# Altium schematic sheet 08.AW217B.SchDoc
size A4; CheckedBy: 赵金生; Author: 黄雄波; CompanyName: 广州周立功的单片机科技有限公司; DocumentNumber: 7; SheetNumber: 7; SheetTotal: 8; PageSetup: Record=PageOptions|CenterHorizontal=True|CenterVertical=True|PrintScale=1.00|XCorrection=1.00|YCorrection=1.00|PrintKind=0|BorderSize=5000000|LeftOffset=0|BottomOffset=0|Orientation=2|PaperLength=1000|PaperWidth=1000|Scale=100|PaperSource=7|PrintQuality=600|MediaType=1|DitherType=10|PaperKind=A4|PrintScaleMode=1; DesignDate: 2018-6-14; CheckDate: 2018-6-14; SheetName: AW217BPT; SheetVersion: V1.01; SheetDescription: AW217BPT 模块; ProductName: 开发套件; ProductModel: AM217BLE
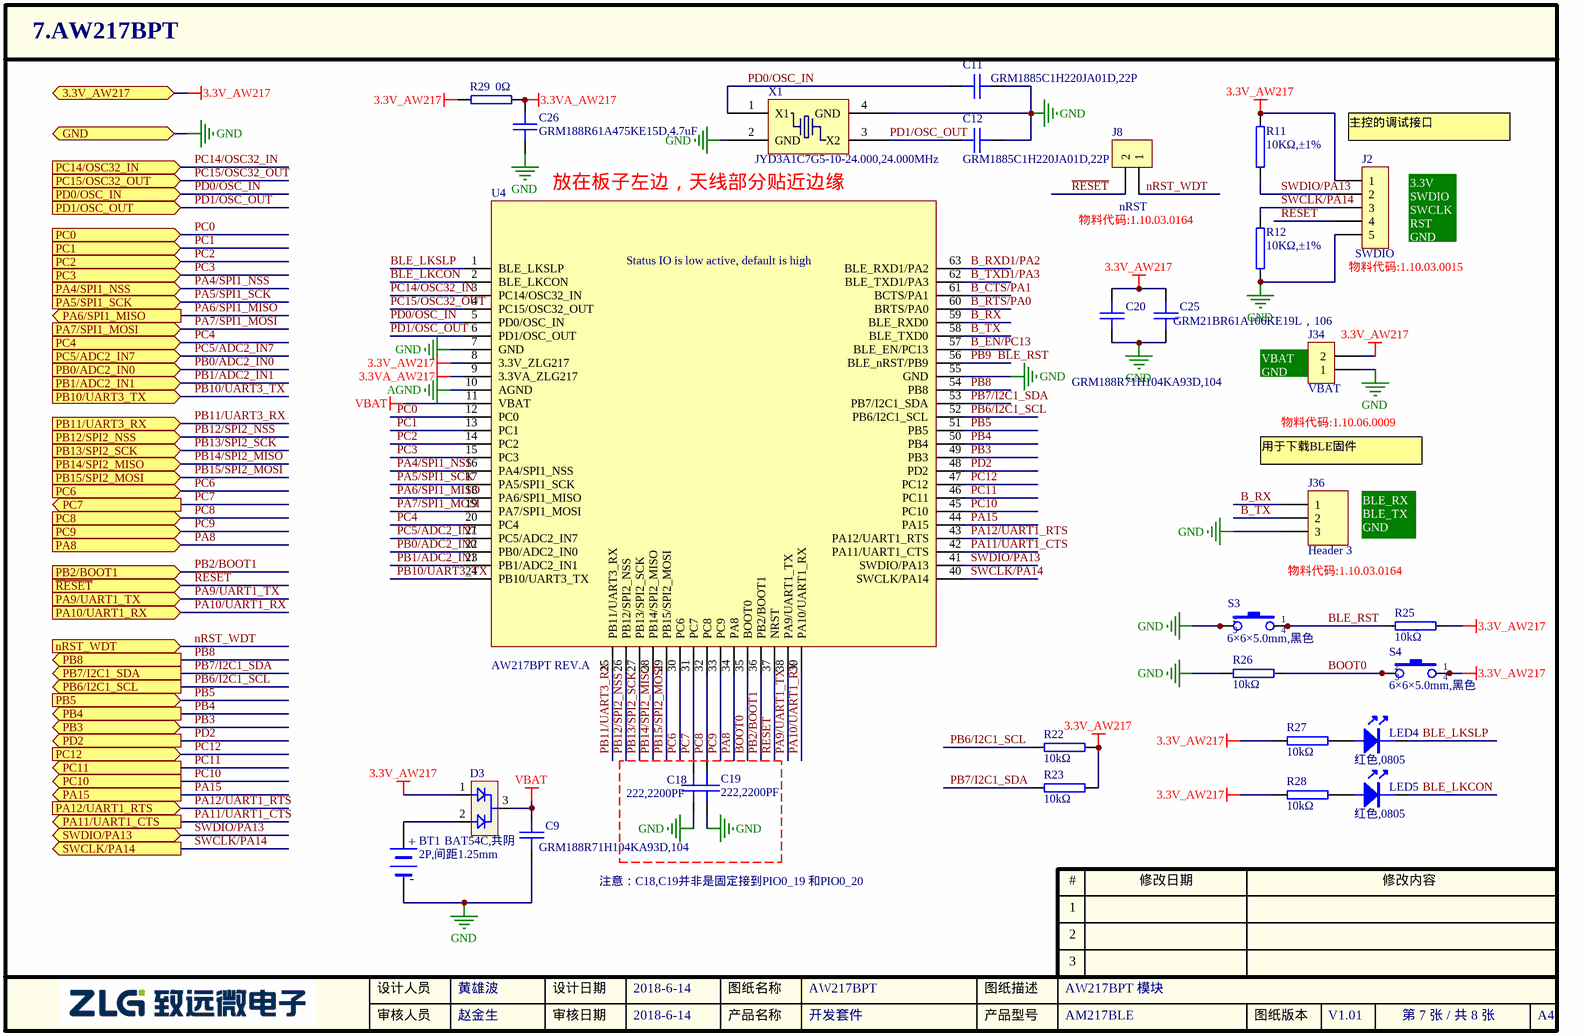
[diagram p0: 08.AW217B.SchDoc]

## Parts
BT1  2P,间距1.25mm  [FPC2-49T]
C9  GRM188R71H104KA93D,104  [0603C]
C11  GRM1885C1H220JA01D,22P  [0603C]
C12  GRM1885C1H220JA01D,22P  [0603C]
C18  222,2200PF  [0603C]
C19  222,2200PF  [0603C]
C20  GRM188R71H104KA93D,104  [0603C]
C25  GRM21BR61A106KE19L，106  [0805C]
C26  GRM188R61A475KE15D,4.7uF  [0603C]
D3  BAT54C,共阴  [SOT-23]
J2  SWDIO  [SIP-5-2.54-6.0-R90]
J8  nRST  [SIP-2-2.54]
J34  VBAT  [CN-2-2.54]
J36  Header 3  [SIP-3-2.54]
LED4  value 红色,0805  [LED-0805]  (hidden comment: LED1)
LED5  value 红色,0805  [LED-0805]  (hidden comment: LED1)
R11  10KΩ,±1%  [0603R]
R12  10KΩ,±1%  [0603R]
R22  10kΩ  [0603R]
R23  10kΩ  [0603R]
R25  10kΩ  [0603R]
R26  10kΩ  [0603R]
R27  10kΩ  [0603R]
R28  10kΩ  [0603R]
R29  0Ω  [0603R]
S3  value 6×6×5.0mm,黑色  [KEY-6S]  (hidden comment: SW-PB4P)
S4  value 6×6×5.0mm,黑色  [KEY-6S]  (hidden comment: SW-PB4P)
U4  AW217BPT REV.A  [AW217BPT]
X1  JYD3A1C7G5-10-24.000,24.000MHz  [OSCCC250X320X80-4N]

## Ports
3.3V_AW217, GND, nRST_WDT (in), PA4/SPI1_NSS (in), PA5/SPI1_SCK (in), PA6/SPI1_MISO (out), PA7/SPI1_MOSI (in), PA8 (in), PA9/UART1_TX (in), PA10/UART1_RX (in), PA11/UART1_CTS (out), PA12/UART1_RTS (in), PA15 (out), PB0/ADC2_IN0 (in), PB1/ADC2_IN1 (in), PB2/BOOT1 (in), PB3 (bidir), PB4 (out), PB5 (in), PB6/I2C1_SCL (out), PB7/I2C1_SDA (out), PB8 (out), PB10/UART3_TX (in), PB11/UART3_RX (in), PB12/SPI2_NSS (in), PB13/SPI2_SCK (in), PB14/SPI2_MISO (in), PB15/SPI2_MOSI (in), PC0 (in), PC1 (in), PC2 (in), PC3 (in), PC4 (in), PC5/ADC2_IN7 (in), PC6 (in), PC7 (out), PC8 (in), PC9 (in), PC10 (out), PC11 (out), PC12 (in), PC14/OSC32_IN (in), PC15/OSC32_OUT (in), PD0/OSC_IN (in), PD1/OSC_OUT (in), PD2 (out), SWCLK/PA14 (out), SWDIO/PA13 (bidir), ~{RESET} (in)

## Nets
3.3V_AW217: C20.1 C25.1 D3.1(D1) J2.1 J34.2 R11.2 R22.2 R23.2 R25.2 R27.1 R28.1 R29.1 S4.1 S4.4 U4.8(3.3V_ZLG217) ; port 3.3V_AW217
3.3VA_AW217: C26.1 R29.2 U4.9(3.3VA_ZLG217)
AGND: U4.10(AGND)
GND: BT1.2(-) C9.2 C11.2 C12.2 C18.2 C19.2 C20.2 C25.2 C26.2 J2.5 J34.1 J36.3 R12.1 R26.1 S3.2 S3.3 U4.7(GND) U4.55(GND) X1.2(GND) X1.4(GND) ; port GND
VBAT: C9.1 D3.3(A) U4.11(VBAT)
B_CTS/PA1: U4.61(BCTS/PA1)
B_EN/PC13: U4.57(BLE_EN/PC13)
B_RTS/PA0: U4.60(BRTS/PA0)
B_RX: J36.1 U4.59(BLE_RXD0)
B_RXD1/PA2: U4.63(BLE_RXD1/PA2)
B_TX: J36.2 U4.58(BLE_TXD0)
B_TXD1/PA3: U4.62(BLE_TXD1/PA3)
BLE_LKCON: LED5.2 U4.2(BLE_LKCON)
BLE_LKSLP: LED4.2 U4.1(BLE_LKSLP)
BLE_RST: R25.1 S3.1 S3.4 U4.56(BLE_nRST/PB9)  [also labelled PB9]
BOOT0: R26.2 S4.2 S4.3 U4.35(BOOT0)
nRST_WDT: J8.1 ; port nRST_WDT
PA4/SPI1_NSS: U4.16(PA4/SPI1_NSS) ; port PA4/SPI1_NSS
PA5/SPI1_SCK: U4.17(PA5/SPI1_SCK) ; port PA5/SPI1_SCK
PA6/SPI1_MISO: U4.18(PA6/SPI1_MISO) ; port PA6/SPI1_MISO
PA7/SPI1_MOSI: U4.19(PA7/SPI1_MOSI) ; port PA7/SPI1_MOSI
PA8: U4.34(PA8) ; port PA8
PA9/UART1_TX: U4.38(PA9/UART1_TX) ; port PA9/UART1_TX
PA10/UART1_RX: U4.39(PA10/UART1_RX) ; port PA10/UART1_RX
PA11/UART1_CTS: U4.42(PA11/UART1_CTS) ; port PA11/UART1_CTS
PA12/UART1_RTS: U4.43(PA12/UART1_RTS) ; port PA12/UART1_RTS
PA15: U4.44(PA15) ; port PA15
PB0/ADC2_IN0: U4.22(PB0/ADC2_IN0) ; port PB0/ADC2_IN0
PB1/ADC2_IN1: U4.23(PB1/ADC2_IN1) ; port PB1/ADC2_IN1
PB2/BOOT1: U4.36(PB2/BOOT1) ; port PB2/BOOT1
PB3: U4.49(PB3) ; port PB3
PB4: U4.50(PB4) ; port PB4
PB5: U4.51(PB5) ; port PB5
PB6/I2C1_SCL: R22.1 U4.52(PB6/I2C1_SCL) ; port PB6/I2C1_SCL
PB7/I2C1_SDA: R23.1 U4.53(PB7/I2C1_SDA) ; port PB7/I2C1_SDA
PB8: U4.54(PB8) ; port PB8
PB10/UART3_TX: U4.24(PB10/UART3_TX) ; port PB10/UART3_TX
PB11/UART3_RX: U4.25(PB11/UART3_RX) ; port PB11/UART3_RX
PB12/SPI2_NSS: U4.26(PB12/SPI2_NSS) ; port PB12/SPI2_NSS
PB13/SPI2_SCK: U4.27(PB13/SPI2_SCK) ; port PB13/SPI2_SCK
PB14/SPI2_MISO: U4.28(PB14/SPI2_MISO) ; port PB14/SPI2_MISO
PB15/SPI2_MOSI: U4.29(PB15/SPI2_MOSI) ; port PB15/SPI2_MOSI
PC0: U4.12(PC0) ; port PC0
PC1: U4.13(PC1) ; port PC1
PC2: U4.14(PC2) ; port PC2
PC3: U4.15(PC3) ; port PC3
PC4: U4.20(PC4) ; port PC4
PC5/ADC2_IN7: U4.21(PC5/ADC2_IN7) ; port PC5/ADC2_IN7
PC6: U4.30(PC6) ; port PC6
PC7: C18.1 U4.31(PC7) ; port PC7
PC8: C19.1 U4.32(PC8) ; port PC8
PC9: U4.33(PC9) ; port PC9
PC10: U4.45(PC10) ; port PC10
PC11: U4.46(PC11) ; port PC11
PC12: U4.47(PC12) ; port PC12
PC14/OSC32_IN: U4.3(PC14/OSC32_IN) ; port PC14/OSC32_IN
PC15/OSC32_OUT: U4.4(PC15/OSC32_OUT) ; port PC15/OSC32_OUT
PD0/OSC_IN: C11.1 U4.5(PD0/OSC_IN) X1.1(X1) ; port PD0/OSC_IN
PD1/OSC_OUT: C12.1 U4.6(PD1/OSC_OUT) X1.3(X2) ; port PD1/OSC_OUT
PD2: U4.48(PD2) ; port PD2
~{RESET}: J2.4 J8.2 U4.37(NRST) ; port ~{RESET}
SWCLK/PA14: J2.3 R12.2 U4.40(SWCLK/PA14) ; port SWCLK/PA14
SWDIO/PA13: J2.2 R11.1 U4.41(SWDIO/PA13) ; port SWDIO/PA13
NetBT1_1: BT1.1(+) D3.2(D2)
NetLED4_1: LED4.1 R27.2
NetLED5_1: LED5.1 R28.2

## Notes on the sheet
- (near J2) 主控的调试接口
- (near C26) 放在板子左边，天线部分贴近边缘
- (near U4) 挖空天线部分板材6mmx20mm
- 物料代码:1.10.03.0164
- (near J2) 3.3V
  SWDIO
  SWCLK
  RST
  GND
- (near J2) 物料代码:1.10.03.0015
- (near J34) VBAT
  GND
- 物料代码:1.10.06.0009
- (near J36) 用于下载BLE固件
- BLE_RX
  BLE_TX
  GND
- 注意：C18,C19并非是固定接到PIO0_19 和PIO0_20

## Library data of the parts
BT1 = 1.10.05.0096: 2P,间距1.25mm,Wafer凹槽边框,90°,FPC2-49T; 名称: 插座; 贴片和直插: SMT; 器件优选方案: 正常状态，可以选用
C9 C20 = 1.02.01.0032: GRM188R71H104KA93D,104,±10%,50V,X7R,0603,muRata,RoHS; 名称: 电容; 封装: 0603; 设备封装名称: C0603_104_X7R_50V_10%; 贴片和直插: SMT; 器件优选方案: 临时/偏门物料/不主推物料，谨慎选用
C11 C12 = 1.02.01.0005: GRM1885C1H220JA01D,22P,±5%,50V,COG,0603,muRata,RoHS; 名称: 电容; 封装: 0603; 设备封装名称: C0603_22P_COG_50V_5%; 贴片和直插: SMT; 器件优选方案: 临时/偏门物料/不主推物料，谨慎选用
C18 C19 = 1.02.01.0048: GRM188R71H222KA01D,222,2200PF,±10%,50V,X7R,0603,RoHS; 名称: 电容; 封装: 0603; 设备封装名称: C0603_222_X7R_50V_10%; 厂商: muRata; 贴片和直插: SMT; 器件优选方案: 正常状态，可以选用
C25 = 1.02.02.0055: GRM21BR61A106KE19L，106,10μF,±10%,10V,X5R,0805,muRata,RoHS; 名称: 电容; 封装: 0805; 设备封装名称: C0805_106_X5R_10V_10%; 贴片和直插: SMT; 器件优选方案: 正常状态，可以选用
C26 = 1.02.01.0080: GRM188R61A475KE15D,4.7uF,±10%,10V,X5R,0603,muRata,RoHS; 名称: 电容; 封装: 0603; 贴片和直插: SMT; PCB备注: 160602yjh; 器件优选方案: 正常状态，可以选用
D3 = 1.04.07.0033: BAT54C,共阴,200mA,30V,SOT-23-3,NXP,RoHS; 名称: 二极管; 贴片和直插: SMT; 器件优选方案: 正常状态，可以选用
J2 = CON5: Connector; 物料代码: 1.10.03.0015
J8 = CON2: Connector; 物料代码: 1.10.03.0164
J34 = 1.10.06.0009: 2.54-2T,180°,,*; 名称: 插座; 贴片和直插: THT; PCB备注: xhm-lq-wyy-150123
J36 = Header 3: Header, 3-Pin; 物料代码: 1.10.03.0164
LED4 LED5 = 1.04.05.0001: 红色,0805,0805,RoHS; 名称: 发光二极管; 封装: 0805; 设备封装名称: LED0805-RED; 贴片和直插: SMT; 器件优选方案: 样品物料,谨慎选用
R11 R12 R22 R23 R25-R28 = 1.01.01.0052: 10KΩ,±1%,0603,*,RoHS; 名称: 电阻; 封装: 0603; 设备封装名称: R0603_10K_1%; 厂商: Ralec; 贴片和直插: SMT
R29 = 1.01.01.0001: 名称: 电阻; 封装: 0603; 设备封装名称: R0603_0R; 厂商: Ralec; 贴片和直插: SMT; 器件优选方案: 状态正常
S3 S4 = 1.09.01.0003: 6×6×5.0mm,黑色,SMD,,*; 名称: 轻触按键; 贴片和直插: SMT
X1 = 1.07.01.0049: JYD3A1C7G5-10-24.000,24.000MHz,10pF,±30ppm,-40~85℃,SMD3225,JYEG,RoHS; 名称: 晶体; 型号: JYD3A1C7G5-10-24.000,24.000MHz,10pF±30ppm,-40~85℃; 贴片和直插: SMT; PCB备注: 171128ZW; 器件优选方案: 正常状态，可以选用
